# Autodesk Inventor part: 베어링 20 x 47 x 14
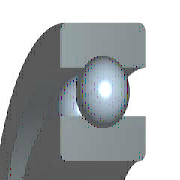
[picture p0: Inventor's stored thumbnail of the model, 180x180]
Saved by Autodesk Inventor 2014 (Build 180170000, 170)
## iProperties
IsCustomPart: 1
Created: 2012-02
Part Number: 베어링 20 x 47 x 14
Material: 강철, 연강
Description: 깊은 그루브 볼 베어링
Document SubType Name: Modeling
Standard: KS B 2023
Designer: mduedu
Standards Organization: KS
Language: ko-KR
Size Designation: 6204 - 20 x 47 x 14
Categories: <MemberInstance><Categories><Category DisplayName="샤프트 부품" InternalName="7f7aeb1f-a693-4053-b835-cee3144e0d98" Mnemonic="SHFT"><Category DisplayName="베어링" Inter
Density: 7.86 g/cm^3
Appearance: 노란색
Mass: 94.2885 g
Surface Area: 87.8912 cm^2
Volume: 11.996 cm^3
Author: mduedu
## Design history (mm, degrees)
sketch "스케치" dims "d0" = 7.02 (= -0.26 x WD + 0.26 x BD)
  geometry: L1 (3.49, 16.75)-(10.51, 16.75); L2 (7, 16.75)-(7, 13.24); L3 (7, 16.75)-(7, 20.26); L4 (4.392, 14.401)-(0, 14.401); L5 (0, 10)-(14, 10); L6 (4.392, 19.099)-(0, 19.099); L7 (0, 23.5)-(14, 23.5); L8 (14, 10)-(14, 14.401); L9 (9.608, 14.401)-(14, 14.401); L10 (9.608, 19.099)-(14, 19.099); L11 (14, 23.5)-(14, 19.099); L12 (-1.4, 0)-(8.4, 0) reference; L13 (0, -0.3)-(0, 5.3) reference
  constraints: 22 end point, 4 point on line, 2 collinear, 2 perpendicular, 2 symmetric about line, 1 midpoint, 1 parallel, 14 other
  dimensions: "d9" = 20 diameter of L5 L12 (= WD); "d11" = 47 diameter of L7 L12 (= BD); "d12" = 14 distance between parallel lines of L8 L13 (= KB); "d13" = 28.802 diameter of L9 L12 (= 0.326 x BD + 0.674 x WD)
revolve "본체" stored, may be unused: angle "d6" = 90 deg
revolve "볼" stored, may be unused: angle "d7" = 90 deg
pattern_circular "IDS_ARRAYBALL[SIMPL:T]" dims angle "d3" = 360 deg
body "Solid1"
fillet "모깎기1" dims "d1" = 1 (= KRS)
other parameters: "WD" = 20 [user parameter; used in 5 equation terms], "BD" = 47 [user parameter; used in 5 equation terms], "KB" = 14 [user parameter; used in 1 equation term], "KRS" = 1 [user parameter; used in 1 equation term], "d4" = 0, "d5" = 0, "d8" = 0, "d14" = 0, "d15" = 0, "BBA" = 0 [user parameter], "BC0" = 6550000 [user parameter], "BC" = 1.27e+07 [user parameter], "BR" = 23.5 (= 0.5 x BD) [user parameter]
